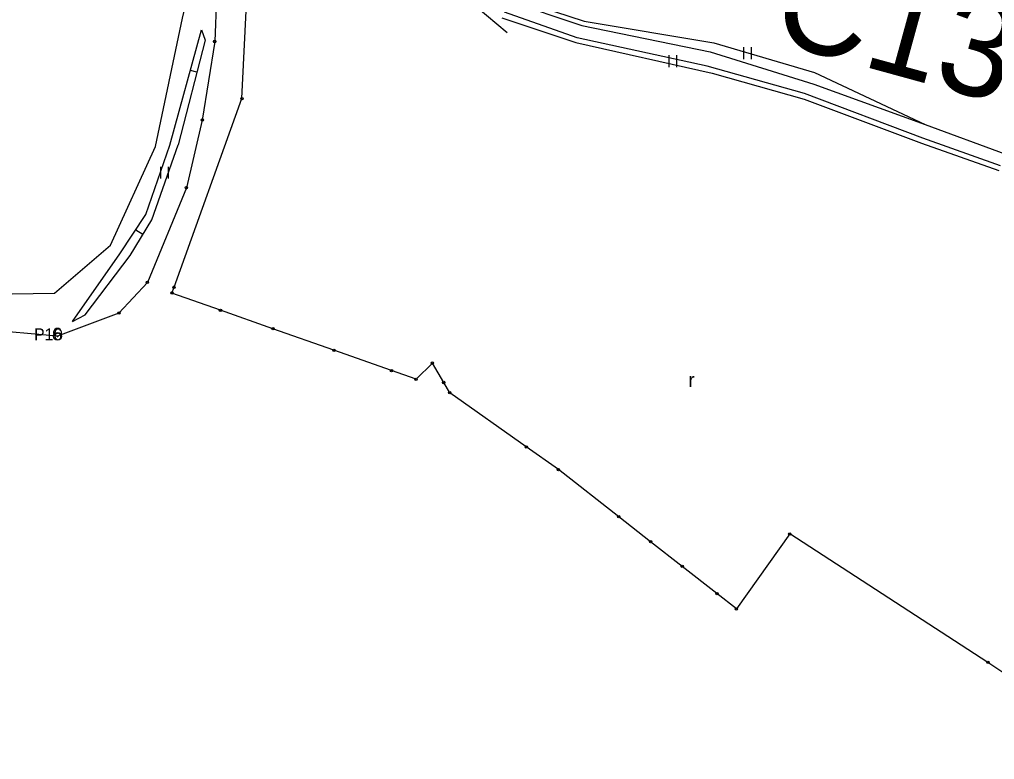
# Model space of a CAD drawing. Extents: x -495905 to -478420, y -1113297 to -1107716.
# Drawn here: x -480676.8 to -480429.6, y -1113177.8 to -1112990.1 of the extents above; entities that cross this region are included whole.
import ezdxf

# ---------------------------------------------------------------- set-up
doc = ezdxf.new("R2010")
doc.units = 0
for name, color, linetype in [('01_OBVOD PÚ', 7, 'Continuous'), ('03_PC_POPIS_NÁVRH', 7, 'Continuous'), ('C14_HLBODY', 7, 'Continuous'), ('ODVODNĚNÍ PLOŠNÉ', 7, 'Continuous'), ('zamereni', 7, 'Continuous')]:
    doc.layers.add(name, color=color, linetype=linetype)

msp = doc.modelspace()

# ---------------------------------------------------------------- linework, layer by layer
at = {"layer": '01_OBVOD PÚ'}
for p, q in [((-480626.02, -1112960.05), (-480627.29, -1112995.69)), ((-480620.4, -1113010.17), (-480618.99, -1112980.09)), ((-480627.29, -1112995.69), (-480630.46, -1113015.6)), ((-480637.62, -1113057.99), (-480620.4, -1113010.17)), ((-480630.46, -1113015.6), (-480634.47, -1113032.77)), ((-480634.47, -1113032.77), (-480644.36, -1113056.78)), ((-480644.36, -1113056.78), (-480651.59, -1113064.57)), ((-480638.16, -1113059.48), (-480637.62, -1113057.99)), ((-480625.84, -1113063.83), (-480638.16, -1113059.48)), ((-480651.59, -1113064.57), (-480667.17, -1113070.45)), ((-480612.53, -1113068.53), (-480625.84, -1113063.83)), ((-480667.17, -1113070.45), (-480690.93, -1113068.31)), ((-480597.07, -1113073.98), (-480612.53, -1113068.53)), ((-480582.47, -1113079.14), (-480597.07, -1113073.98)), ((-480576.26, -1113081.33), (-480582.47, -1113079.14)), ((-480572.1, -1113077.25), (-480576.26, -1113081.33)), ((-480569.22, -1113082.16), (-480572.1, -1113077.25)), ((-480567.7, -1113084.75), (-480569.22, -1113082.16)), ((-480548.3, -1113098.48), (-480567.7, -1113084.75)), ((-480540.16, -1113104.24), (-480548.3, -1113098.48)), ((-480524.85, -1113116.22), (-480540.16, -1113104.24)), ((-480516.76, -1113122.54), (-480524.85, -1113116.22)), ((-480481.47, -1113120.55), (-480495, -1113139.56)), ((-480431.23, -1113153.14), (-480481.47, -1113120.55)), ((-480508.76, -1113128.8), (-480516.76, -1113122.54)), ((-480499.93, -1113135.7), (-480508.76, -1113128.8)), ((-480495, -1113139.56), (-480499.93, -1113135.7)), ((-480394.92, -1113177.76), (-480431.23, -1113153.14))]:
    msp.add_line(p, q, dxfattribs=at)
at = {"layer": 'C14_HLBODY'}
msp.add_line((-480575.77, -1112974.2), (-480553.1, -1112993.4), dxfattribs=at)
at = {"layer": 'ODVODNĚNÍ PLOŠNÉ'}
msp.add_lwpolyline([(-480694.9, -1113059.94), (-480667.93, -1113059.49), (-480653.74, -1113047.32), (-480642.35, -1113022.32), (-480635.5, -1112989.75), (-480627.89, -1112957.21), (-480579.74, -1112948.18), (-480566.18, -1112926.07), (-480548.4, -1112906.66), (-480531.37, -1112886.97), (-480511.79, -1112867.13), (-480489.05, -1112844.36), (-480463.74, -1112827.55), (-480444.49, -1112809.73), (-480465.44, -1112785.99), (-480488.34, -1112766.74), (-480513.53, -1112747.67), (-480541.81, -1112722.86), (-480567.11, -1112699.96), (-480605.77, -1112673.98)], dxfattribs=at)
at = {"layer": 'zamereni'}
for p, q in [((-480552.85, -1112985.36), (-480534.17, -1112991.67)), ((-480552.53, -1112984.33), (-480533.63, -1112990.53)), ((-480554.49, -1112989.66), (-480535.7, -1112995.91)), ((-480535.37, -1112994.8), (-480553.85, -1112988.22)), ((-480533.63, -1112990.53), (-480500.71, -1112996.07)), ((-480638.68, -1113021.99), (-480630.64, -1112992.73)), ((-480630.64, -1112992.73), (-480629.77, -1112995.31)), ((-480534.17, -1112991.67), (-480501.64, -1112998.31)), ((-480629.77, -1112995.31), (-480636.61, -1113021.93)), ((-480502.41, -1113001.97), (-480535.37, -1112994.8)), ((-480535.7, -1112995.91), (-480501.17, -1113003.71)), ((-480500.71, -1112996.07), (-480475.16, -1113003.55)), ((-480493.21, -1112997.16), (-480493.21, -1113000.16)), ((-480491.17, -1113000.16), (-480491.17, -1112997.16)), ((-480512.15, -1112999.17), (-480512.15, -1113002.17)), ((-480510.11, -1113002.17), (-480510.11, -1112999.17)), ((-480501.64, -1112998.31), (-480475.33, -1113006.5)), ((-480477.76, -1113008.85), (-480502.41, -1113001.97)), ((-480631.86, -1113003.44), (-480633.43, -1113003.04)), ((-480501.17, -1113003.71), (-480477.85, -1113010.35)), ((-480475.16, -1113003.55), (-480447.12, -1113016.74)), ((-480475.33, -1113006.5), (-480447.12, -1113016.74)), ((-480477.85, -1113010.35), (-480448.1, -1113021.46)), ((-480447.7, -1113020.19), (-480477.76, -1113008.85)), ((-480447.12, -1113016.74), (-480426.97, -1113024.18)), ((-480428, -1113027.24), (-480447.7, -1113020.19)), ((-480644.79, -1113039.53), (-480638.68, -1113021.99)), ((-480643.28, -1113040.93), (-480636.61, -1113021.93)), ((-480448.1, -1113021.46), (-480428.48, -1113028.38)), ((-480641.05, -1113027.47), (-480641.05, -1113030.47)), ((-480639.01, -1113030.47), (-480639.01, -1113027.47)), ((-480651.37, -1113049.54), (-480644.79, -1113039.53)), ((-480648.75, -1113049.96), (-480643.28, -1113040.93)), ((-480645.52, -1113044.62), (-480647.27, -1113043.56)), ((-480663.4, -1113066.73), (-480651.37, -1113049.54)), ((-480660.19, -1113065.01), (-480648.75, -1113049.96)), ((-480663.4, -1113066.73), (-480660.19, -1113065.01))]:
    msp.add_line(p, q, dxfattribs=at)
for centre in [(-480627.29, -1112995.69), (-480620.4, -1113010.17), (-480630.46, -1113015.6), (-480634.47, -1113032.77), (-480644.36, -1113056.78), (-480638.16, -1113059.48), (-480637.62, -1113057.99), (-480651.59, -1113064.57), (-480625.84, -1113063.83), (-480612.53, -1113068.53), (-480597.07, -1113073.98), (-480572.1, -1113077.25), (-480582.47, -1113079.14), (-480576.26, -1113081.33), (-480569.22, -1113082.16), (-480567.7, -1113084.75), (-480548.3, -1113098.48), (-480540.16, -1113104.24), (-480524.85, -1113116.22), (-480481.47, -1113120.55), (-480516.76, -1113122.54), (-480508.76, -1113128.8), (-480499.93, -1113135.7), (-480495, -1113139.56), (-480431.23, -1113153.14)]:
    msp.add_circle(centre, 0.3, dxfattribs=at)
msp.add_ellipse((-480667.17, -1113069.45), major_axis=(0, -1), ratio=0.999955, start_param=1.047987, end_param=5.236518, dxfattribs=at)
for major_axis in [(0, -1), (0, -0.133)]:
    msp.add_ellipse((-480667.17, -1113070.45), major_axis=major_axis, ratio=0.999955, dxfattribs=at)

# ---------------------------------------------------------------- texts
at = {"layer": '03_PC_POPIS_NÁVRH'}
msp.add_text('C13', height=25, rotation=344.669, dxfattribs=at).set_placement((-480486.98, -1112995.36))
at = {"layer": 'zamereni'}
for s, height, p in [('P16', 3, (-480673.12, -1113071.45)), ('r', 3.6, (-480507.18, -1113083.29))]:
    msp.add_text(s, height=height, dxfattribs=at).set_placement(p)

doc.saveas('drawing.dxf')
